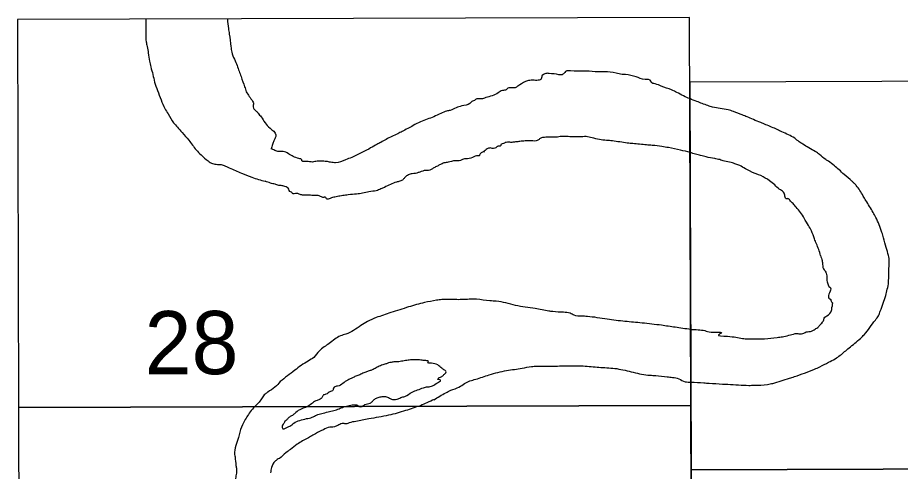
# Model space of a CAD drawing. Extents: x 3329332 to 3367211, y 631066 to 656469.
# Drawn here: x 3354025 to 3355661, y 634743 to 635584 of the extents above; entities that cross this region are included whole.
import ezdxf

# ---------------------------------------------------------------- set-up
doc = ezdxf.new("R2010")
doc.units = 0
doc.layers.add('V-ANNO-NPLT', color=7, linetype='Continuous')

msp = doc.modelspace()

# ---------------------------------------------------------------- linework, layer by layer
at = {"layer": 'V-ANNO-NPLT'}
for points in [[(3354026.3, 634861.8), (3355272.6, 634865.5), (3355270.2, 635583.7), (3354024.5, 635580.1), (3354026.3, 634861.8)], [(3355273, 634745.8), (3356519.5, 634750.5), (3356516.4, 635468.7), (3355270.6, 635464), (3355273, 634745.8)], [(3354028.1, 634143.6), (3355275, 634147.3), (3355272.6, 634865.5), (3354026.3, 634861.8), (3354028.1, 634143.6)], [(3355275.4, 634027.5), (3356522.5, 634032.3), (3356519.5, 634750.5), (3355273, 634745.8), (3355275.4, 634027.5)]]:
    msp.add_lwpolyline(points, dxfattribs=at)
for points in [[(3354262.3, 635580.7), (3354262.3, 635552), (3354262.7, 635539.2), (3354264.7, 635530.3), (3354266.6, 635518.3), (3354269, 635503.1), (3354271.3, 635492.7), (3354275.2, 635478.3), (3354278.4, 635464.4), (3354283.8, 635448.9)], [(3354413.4, 635581.2), (3354415.2, 635563.5), (3354416.8, 635553.4), (3354419.9, 635530.2), (3354421.5, 635519.7), (3354426.2, 635506.9), (3354431.2, 635494.9), (3354438.6, 635474.4), (3354445.3, 635455.8)], [(3355037.8, 635480.9), (3355032.6, 635477.6), (3355028, 635478), (3355009.7, 635480.3), (3355003.6, 635480.3), (3355000.3, 635478.9), (3354997.1, 635477), (3354995.2, 635470.5), (3354989.6, 635467.7), (3354984.4, 635467.6), (3354973.7, 635467.6), (3354965.7, 635465.3), (3354951.7, 635456.8), (3354946.5, 635454), (3354941.4, 635453.5), (3354933.4, 635453), (3354930.2, 635450.2), (3354923.1, 635448.8), (3354915.2, 635444.6), (3354904, 635438.9), (3354892.3, 635435.6), (3354883.8, 635433.2), (3354873.5, 635432.3), (3354871.2, 635430.4), (3354867.5, 635429), (3354862.8, 635424.8), (3354847.8, 635420.1), (3354837.1, 635416.7)], [(3355270.7, 635433.7), (3355258.8, 635438.6), (3355246.7, 635445.2), (3355236.8, 635449.8), (3355217.6, 635456.8), (3355206.4, 635461), (3355198.9, 635464.3), (3355198.4, 635466.2), (3355187.6, 635469.4), (3355170.8, 635474.1), (3355151.1, 635478.3), (3355145, 635478.7), (3355133.8, 635481.1), (3355112.2, 635483.4), (3355100.5, 635483.3), (3355078, 635484.7), (3355068.7, 635484.7), (3355042.9, 635485.1), (3355042.5, 635485.1), (3355037.8, 635480.9)], [(3354445.3, 635455.8), (3354448.4, 635446.5), (3354460, 635429.1), (3354461.6, 635425.2), (3354461.2, 635421.3), (3354461.6, 635416.3), (3354466.2, 635411.3), (3354470.1, 635406.6), (3354476, 635400)], [(3354283.8, 635448.9), (3354290.4, 635431.5), (3354297.4, 635415.2), (3354303.3, 635405.5), (3354313.7, 635388.9), (3354320.7, 635381.1)], [(3355402, 635389.5), (3355388.5, 635394.8), (3355376.8, 635400), (3355367.7, 635403.4), (3355351.5, 635409.8), (3355341.3, 635412.8), (3355312.7, 635418), (3355304, 635420.7), (3355283.3, 635428.5), (3355270.7, 635433.7)], [(3354837.1, 635416.7), (3354826.3, 635412), (3354819.7, 635410.6), (3354809, 635406.3), (3354795.9, 635400.2), (3354783.7, 635395.5), (3354771.1, 635390.8), (3354757.5, 635383.7), (3354737.4, 635372.9), (3354729, 635368.7), (3354707.5, 635358.3), (3354697.7, 635352.7), (3354690.6, 635348.9)], [(3354476, 635400), (3354492.3, 635379.1), (3354503.1, 635366.4), (3354502, 635360.9), (3354499.7, 635355.5), (3354497, 635348.9), (3354495.8, 635344.6), (3354494.4, 635340.6)], [(3354320.7, 635381.1), (3354329.3, 635370.7), (3354341.7, 635356.8), (3354355.6, 635338.6), (3354364.6, 635329.3), (3354377.4, 635318.4), (3354385.9, 635313.4), (3354394.8, 635311.9), (3354403.7, 635311.1), (3354411.5, 635307.7), (3354416.9, 635305.7)], [(3355503.1, 635335.8), (3355491.1, 635342.5), (3355480.1, 635349.3), (3355473.3, 635353.8), (3355465, 635360.2), (3355440.9, 635372.3), (3355432.6, 635376.4), (3355411.5, 635385.4), (3355402, 635389.5)], [(3355037.9, 635363.7), (3355032.4, 635363.7), (3355022.6, 635362.3), (3355013.2, 635362.2), (3355003.8, 635362.2), (3354998.7, 635361.7), (3354993.1, 635359.9), (3354991.2, 635358), (3354986, 635355.6), (3354973.4, 635355.6), (3354962.6, 635355.1), (3354953.3, 635354.2), (3354945.8, 635353.2), (3354938.8, 635352.7), (3354930.3, 635352.7), (3354922.9, 635349.9), (3354920.5, 635348.5), (3354920.1, 635346.6), (3354916.8, 635345.7), (3354914.9, 635345.7), (3354913, 635344.2), (3354904.1, 635341.4), (3354900.4, 635342.3), (3354894.8, 635340.5), (3354887.8, 635334.8)], [(3355271.1, 635333.8), (3355253.4, 635338.3), (3355230.9, 635343), (3355218.8, 635344.8), (3355201, 635347.1), (3355190.2, 635348), (3355164.9, 635350.3), (3355154.6, 635351.3), (3355127, 635355.4), (3355116.2, 635356.3), (3355089.5, 635361), (3355078.3, 635363.3), (3355066.6, 635362.8), (3355058.1, 635362.8), (3355047.8, 635363.2), (3355037.1, 635363.7)], [(3354690.6, 635348.9), (3354678.9, 635342.3), (3354664, 635334.3), (3354643.9, 635324.9), (3354632.2, 635320.2), (3354613.9, 635315), (3354604.6, 635315.9), (3354596.6, 635317.3), (3354587.2, 635317.8), (3354579.7, 635317.8), (3354570.8, 635316.3), (3354560.1, 635317.3), (3354551.6, 635318.7), (3354551.2, 635320.1), (3354546, 635322.9), (3354526.3, 635331.7), (3354517, 635335.9), (3354509, 635335.9), (3354501, 635337.8), (3354494.5, 635340.6), (3354494.4, 635340.6)], [(3354888.8, 635335.7), (3354880.8, 635329.1), (3354880.3, 635327.7), (3354878.4, 635327.7), (3354867.7, 635324.4), (3354855.5, 635322), (3354850.8, 635321.6), (3354845.2, 635319.2), (3354835.4, 635318.7), (3354822.7, 635315.9), (3354814.8, 635314.5), (3354808.2, 635311.6), (3354802.6, 635308.8), (3354796.1, 635305.5), (3354790.9, 635302.2), (3354786.2, 635300.4), (3354783.4, 635300.8), (3354772.7, 635298.5), (3354767, 635296.6), (3354761.9, 635295.2), (3354755.8, 635294.7), (3354748.8, 635292.3), (3354742.7, 635288.1), (3354739, 635283.9), (3354732.9, 635280.6), (3354726.8, 635279.1), (3354704.4, 635269.3)], [(3355326.1, 635320.7), (3355316.6, 635322.6), (3355300.8, 635325.6), (3355290.6, 635328.6), (3355281.2, 635330.8), (3355271.1, 635333.8)], [(3355596.8, 635245), (3355591.8, 635253.3), (3355579, 635272.9), (3355574.8, 635277.4), (3355571.1, 635280.8), (3355556.7, 635292.9), (3355547.3, 635301.9), (3355538.6, 635309.4), (3355527.3, 635317.7), (3355522.4, 635320.7), (3355511.1, 635330.1), (3355503.1, 635335.8)], [(3355402.2, 635291.1), (3355385.6, 635297.8), (3355383.4, 635299), (3355373.6, 635303.8), (3355363, 635309.9), (3355355.8, 635312.5), (3355347.2, 635315.1), (3355334.7, 635317.7), (3355326.1, 635320.7)], [(3354416.9, 635305.7), (3354439.4, 635295.7), (3354458.7, 635288), (3354483.4, 635280.6)], [(3354704.4, 635269.3), (3354697.8, 635266.4), (3354689.4, 635263.1), (3354675.8, 635261.2), (3354663.7, 635258.4), (3354652.9, 635257), (3354637.4, 635255.5), (3354627.1, 635254.1), (3354622, 635253.2), (3354612.6, 635251.3), (3354603.7, 635248.9), (3354597.2, 635248), (3354595.8, 635250.8), (3354593.4, 635251.2), (3354592, 635250.8), (3354583.6, 635253.6), (3354579.4, 635254.5), (3354572.4, 635254.5), (3354562.5, 635254.9), (3354552.7, 635254.9), (3354546.6, 635256.8), (3354541.5, 635258.2), (3354534, 635258.2), (3354532.1, 635260.5), (3354528.8, 635261.4), (3354526.9, 635266.1), (3354519.9, 635270.8), (3354512.9, 635272.7), (3354508.7, 635273.1), (3354501.6, 635275), (3354493.2, 635277.3), (3354483.4, 635280.6)], [(3355461.9, 635239.5), (3355455.8, 635245.5), (3355452.4, 635248.5), (3355451.7, 635248.2), (3355450.9, 635247.8), (3355449.4, 635248.2), (3355447.1, 635251.2), (3355446.4, 635254.9), (3355445.3, 635258.7), (3355438.5, 635264.7), (3355436.2, 635266.2), (3355427.9, 635273.8), (3355418.1, 635281.7), (3355402.2, 635291.1)], [(3355638.8, 635143.3), (3355634.6, 635158), (3355629.7, 635175.7), (3355626.6, 635185.9), (3355615.3, 635213.8), (3355610.4, 635222.8), (3355596.8, 635245)], [(3355512.9, 635143), (3355509.5, 635154.3), (3355505.3, 635164.9), (3355501.6, 635173.9), (3355495.9, 635189), (3355490.6, 635198.4), (3355482.6, 635212), (3355475.8, 635222.9), (3355467.5, 635232.7), (3355461.9, 635239.5)], [(3355512.9, 635143), (3355515.6, 635133.6), (3355516.7, 635126.4), (3355519.4, 635116.3), (3355521.6, 635114), (3355524.3, 635105.7), (3355525.1, 635094.4), (3355527.7, 635087.2), (3355528.5, 635085.3), (3355530.4, 635084.2), (3355530.8, 635077.1), (3355527.8, 635066.1), (3355530, 635062.7), (3355531.2, 635062.3), (3355531.9, 635060.1), (3355533.4, 635057.1), (3355534.9, 635055.2), (3355534.6, 635053.3), (3355534.2, 635048.8)], [(3355623.5, 635040.3), (3355633.6, 635069.3), (3355634.8, 635074.6), (3355638.1, 635087.1), (3355639.2, 635100.6), (3355639.6, 635119.5), (3355640.3, 635132.3), (3355638.8, 635143.3)], [(3354984, 635045.2), (3354947.3, 635050.6), (3354911.8, 635058.5), (3354899.6, 635059.1), (3354875.2, 635062.1), (3354848.3, 635061.4), (3354835.4, 635061.4), (3354811, 635061.4), (3354801.2, 635060.1), (3354778.6, 635055.8), (3354749.3, 635047.8), (3354716.3, 635037.3), (3354688.8, 635028.1)], [(3355465.3, 634998.4), (3355471, 634998.5), (3355477.5, 634998), (3355486.4, 635001.5), (3355491, 635002.3), (3355497.4, 635003.4), (3355502.6, 635006.5), (3355509.4, 635011.4), (3355513.5, 635016.3), (3355516.5, 635019.7), (3355519.2, 635025.3), (3355520.7, 635028.7), (3355524.8, 635031.4), (3355533.1, 635041.2), (3355534.2, 635048.8)], [(3355272.2, 635006), (3355243.2, 635010.2), (3355218.1, 635013.8), (3355182, 635018), (3355150.3, 635021), (3355117.3, 635025.2), (3355080.6, 635030.1), (3355069.6, 635030.7), (3355056.1, 635032.5), (3355048.8, 635036.1), (3355036.6, 635037.9), (3355016.4, 635039.1), (3355009.1, 635040.3), (3354984, 635045.2)], [(3355464.6, 634918.7), (3355501.6, 634932.5), (3355511.8, 634937.1), (3355527.6, 634945.4), (3355539.7, 634951.8), (3355549.4, 634958.3), (3355565.6, 634971.9), (3355576.5, 634980.6), (3355586.7, 634989.6), (3355593.8, 634996.4), (3355614.5, 635023.6), (3355620.5, 635031.6), (3355623.5, 635040.3)], [(3354688.8, 635028.1), (3354673, 635020.7), (3354660.8, 635013.3), (3354632.7, 634997.4), (3354622.9, 634994.3), (3354602.1, 634980.2), (3354583.8, 634966.7), (3354573.5, 634954.4), (3354563.1, 634947.7), (3354538.1, 634930.5), (3354511.2, 634909.6)], [(3355272.2, 635006), (3355298.1, 635003.9), (3355309.8, 635001.3), (3355328.9, 634999.4), (3355323.5, 634996.2), (3355340.2, 634993.5), (3355367.9, 634989.5), (3355378.4, 634988.8), (3355399.3, 634989), (3355409.2, 634989), (3355432.3, 634991.3), (3355442.1, 634992.7), (3355465.8, 634998.5)], [(3354645, 634916.3), (3354636.4, 634912.5), (3354617.6, 634901.2), (3354611.2, 634899.1), (3354609.6, 634895.8), (3354609.1, 634894.2), (3354608, 634892.6), (3354604.2, 634891), (3354595.7, 634886.1), (3354590.8, 634884), (3354589.8, 634881.8), (3354588.1, 634879.7), (3354585.5, 634877), (3354579.6, 634874.8), (3354562.9, 634864), (3354552.7, 634859.7), (3354547.4, 634857.5), (3354537.7, 634850), (3354532.4, 634846.2), (3354527, 634843), (3354523.8, 634839.2), (3354520, 634836), (3354517.9, 634832.2), (3354515.7, 634829), (3354514.7, 634825.7), (3354515.2, 634823.1), (3354517.4, 634822), (3354520, 634822.5), (3354524.9, 634825.2), (3354532.9, 634829.5), (3354536.7, 634832.8), (3354547.4, 634837.6), (3354559.8, 634840.9), (3354570.5, 634843.6), (3354578.5, 634847.4), (3354588.2, 634850.6), (3354600, 634853.3), (3354610.7, 634856), (3354620.4, 634859.3), (3354628.5, 634862.5), (3354639.2, 634865.2), (3354644.6, 634866.3), (3354649.9, 634866.3), (3354653.2, 634866.3), (3354656.9, 634863.7), (3354662.8, 634863.7), (3354668.2, 634866.9), (3354677.9, 634869.6), (3354680.5, 634871.2), (3354682.1, 634872.8), (3354686.4, 634877.1), (3354692.9, 634879.8), (3354700.4, 634882), (3354704.7, 634882), (3354711.7, 634879.9), (3354716, 634877.7), (3354722.4, 634876.1), (3354727.8, 634876.7), (3354734.8, 634879.9), (3354742.3, 634882.1), (3354755.7, 634890.2), (3354765.9, 634894), (3354776.6, 634898.3), (3354784.7, 634899.9), (3354793.8, 634901.5), (3354802.9, 634907.5), (3354808.3, 634911.8), (3354806.1, 634913.4), (3354803.5, 634913.4), (3354804, 634915.5), (3354808.3, 634917.7), (3354812.6, 634920.4), (3354816.9, 634924.7), (3354819, 634927.4), (3354816.3, 634930.6), (3354810.9, 634934.4), (3354803.4, 634940.3), (3354791.6, 634943.5), (3354788.9, 634943.5), (3354785.1, 634944), (3354786.2, 634947.2), (3354783, 634948.3), (3354776.5, 634948.8), (3354767.4, 634949.9), (3354762, 634949.9), (3354755, 634949.9), (3354745.9, 634948.8), (3354736.3, 634947.1), (3354731.4, 634946.1), (3354723.4, 634946), (3354716.9, 634945)], [(3354716.9, 634945), (3354712.1, 634944.4), (3354707.3, 634942.2), (3354703.5, 634941.2), (3354694.9, 634937.9), (3354687.4, 634934.1), (3354679.4, 634930.4), (3354672.9, 634928.2), (3354666.5, 634926), (3354659, 634922.3), (3354651.4, 634919.6), (3354645, 634916.3)], [(3354796.1, 634876), (3354818.1, 634888.9), (3354827.8, 634893.8), (3354842.5, 634899.3), (3354852.9, 634906.1), (3354873.6, 634914), (3354898.7, 634922), (3354931, 634930.1), (3354959.7, 634934.4), (3354976.9, 634937.5), (3354987.2, 634938.1)], [(3354987.2, 634938.1), (3355017.2, 634938.2), (3355048.4, 634938.9), (3355076.5, 634938.3), (3355105.8, 634935.9), (3355135.1, 634933.5), (3355165.7, 634926.8), (3355196.9, 634921.4), (3355207.3, 634920.8), (3355228.7, 634918.4), (3355238.5, 634917.2), (3355250.1, 634914.8), (3355261.7, 634909.3), (3355267.2, 634908.7), (3355272.5, 634908.7)], [(3355272.5, 634908.7), (3355296.5, 634907.2), (3355306.3, 634906.6), (3355331, 634905), (3355341.1, 634904.5), (3355380, 634902.6), (3355389.9, 634902.8), (3355414.5, 634904.4), (3355424.2, 634906.3), (3355455.2, 634915.9), (3355464.6, 634918.7)], [(3354511.2, 634909.6), (3354501.5, 634899.2), (3354488, 634890), (3354483.2, 634886.3), (3354477.7, 634879.6), (3354472.2, 634871.6), (3354463.7, 634863.1)], [(3354797.2, 634876.6), (3354783.3, 634870.4), (3354771, 634864.9)], [(3354463.7, 634863.1), (3354455.6, 634853.3), (3354443.8, 634834.2), (3354436.2, 634815.8), (3354433.9, 634806.2), (3354429, 634790.9), (3354426.7, 634774.5), (3354427.5, 634769.9), (3354429.1, 634753.9), (3354430.2, 634747.7)], [(3354771, 634864.9), (3354743.5, 634855.7), (3354712.2, 634847.3), (3354675.5, 634840.3), (3354651.5, 634835.7), (3354638.9, 634833), (3354630.9, 634831.4), (3354629, 634832.2), (3354625.9, 634831.8), (3354617.9, 634828.4), (3354611.8, 634825.7), (3354606.1, 634825.3), (3354603.4, 634825.3), (3354591.2, 634820.3)], [(3354591.6, 634820.5), (3354576.7, 634813), (3354567.2, 634807.6), (3354552.7, 634799.6), (3354542.8, 634793.4), (3354530.2, 634783.9), (3354521.8, 634777.7), (3354509.6, 634767.4), (3354505.8, 634765.1), (3354501.6, 634762), (3354495.1, 634750.5), (3354493.2, 634740.6)], [(3354430.2, 634747.7), (3354429.9, 634740.1), (3354428.3, 634730.2), (3354428, 634724.4), (3354428.4, 634719.5), (3354430.7, 634713.7), (3354436.8, 634690.4), (3354440.7, 634679.7), (3354447.6, 634662.5)]]:
    msp.add_spline(points, degree=3, dxfattribs=at)

# ---------------------------------------------------------------- texts
msp.add_text('28', height=117, rotation=0.1083, dxfattribs=at).set_placement((3354259.9, 634923.1))

doc.saveas('drawing.dxf')
